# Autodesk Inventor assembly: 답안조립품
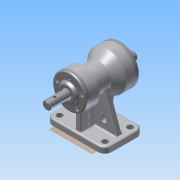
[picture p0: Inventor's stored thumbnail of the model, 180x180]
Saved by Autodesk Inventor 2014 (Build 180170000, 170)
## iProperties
Created: 2015-08
Part Number: 답안조립품
Document SubType Name: Assembly
Designer: sda20
Author: sda20
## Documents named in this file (10)
- C:\Users\sda20\Desktop\450805V1007\답안조립품.iam
- C:\Users\sda20\Desktop\450805V1007\답안부품.ipt
- C:\Users\sda20\Desktop\450805V1007\축.ipt
- C:\Users\sda20\Desktop\450805V1007\베어링 6203.ipt
- C:\Users\sda20\Desktop\450805V1007\뒤커버.ipt
- C:\Users\sda20\Desktop\450805V1007\베어링 6205.ipt
- C:\Users\sda20\Desktop\450805V1007\앞커버.ipt
- C:\Users\sda20\Desktop\450805V1007\M4x0.5.ipt
- C:\Users\sda20\Desktop\450805V1007\오일실 .ipt
- 오일실 .ipt
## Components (2 placed, 1 different names)
1. M4x0.5:1
2. M4x0.5:2
